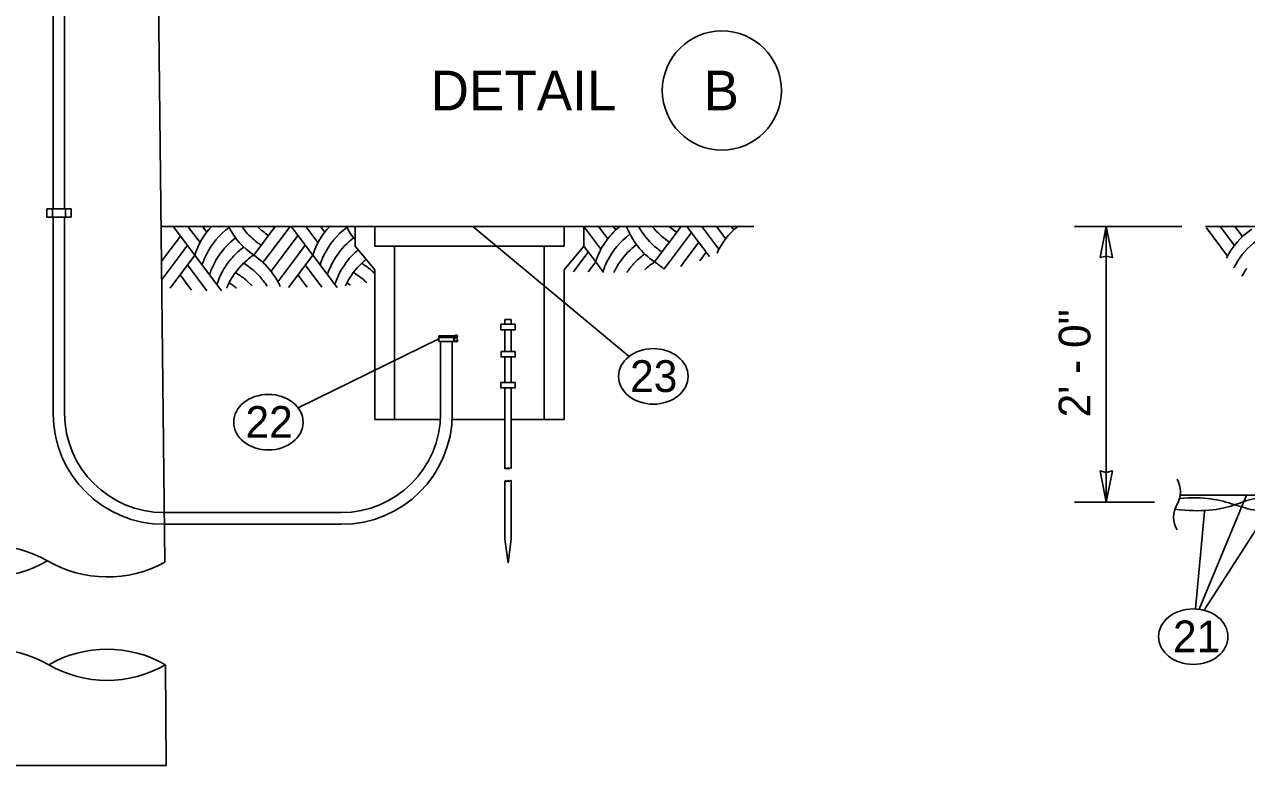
# Model space of a CAD drawing. Extents: x 99862 to 104211, y 98939 to 102076.
# Drawn here: x 100173 to 100788, y 100738 to 101111 of the extents above; entities that cross this region are included whole.
import ezdxf

# ---------------------------------------------------------------- set-up
doc = ezdxf.new("R2010")
doc.units = 0
for name, color, linetype in [('Level 1', 7, 'Continuous'), ('Level 11', 7, 'Continuous'), ('Level 13', 7, 'Continuous'), ('Level 15', 7, 'Continuous'), ('Level 20', 7, 'Continuous'), ('Level 7', 7, 'Continuous'), ('Level 8', 7, 'Continuous')]:
    doc.layers.add(name, color=color, linetype=linetype)

msp = doc.modelspace()

# ---------------------------------------------------------------- linework, layer by layer
at = {"layer": 'Level 1'}
for p, q in [((100243.61, 100840.23), (100238.01, 101340.94)), ((100244.35, 100737.75), (100243.96, 100788.54)), ((100244.35, 100737.75), (100124.97, 100737.75))]:
    msp.add_line(p, q, dxfattribs=at)
for centre, radius, start, end in [((100155.12, 100789.93), 58.82, 60, 120), ((100155.12, 100891.81), 58.82, 240, 300), ((100214.64, 100893.22), 60.4, 240.09406, 298.66389), ((100155.25, 100736.77), 59.78, 60, 120), ((100214.55, 100737.6), 58.82, 60, 120), ((100214.55, 100839.49), 58.82, 240, 300)]:
    msp.add_arc(centre, radius, start, end, dxfattribs=at)
at = {"layer": 'Level 11'}
msp.add_line((100810.77, 100874.11), (100755.06, 100874.11), dxfattribs=at)
for points in [[(100809.24, 100871.12), (100794.89, 100874.79), (100783.46, 100867.92), (100766.15, 100865.27), (100752.4, 100866.99)], [(100809.24, 100867.94), (100796.06, 100864.31), (100783.06, 100869.64), (100766.93, 100873.64), (100754.71, 100872.33)]]:
    msp.add_open_spline(points, degree=3, dxfattribs=at)
at = {"layer": 'Level 13'}
for p, q in [((100339.44, 101009.51), (100241.94, 101009.51)), ((100242.13, 100992.19), (100251.48, 101004.66)), ((100247.84, 101009.51), (100258.71, 100995.02)), ((100255.27, 101009.51), (100261.39, 101001.35)), ((100262.69, 101009.51), (100264.83, 101006.66)), ((100288.41, 100995.02), (100299.28, 101009.51)), ((100295.83, 100995.02), (100306.7, 101009.51)), ((100303.26, 100995.02), (100310.68, 101004.92)), ((100307.24, 101009.51), (100318.11, 100995.02)), ((100314.66, 101009.51), (100320.78, 101001.35)), ((100322.09, 101009.51), (100324.22, 101006.66)), ((100454.61, 101009.51), (100540.36, 101009.51)), ((100454.66, 101009.51), (100463.32, 100997.97)), ((100462.09, 101009.51), (100466.76, 101003.28)), ((100469.51, 101009.51), (100470.84, 101007.74)), ((100490.34, 100991.63), (100503.75, 101009.51)), ((100497.77, 100991.63), (100508.91, 101006.48)), ((100506.63, 101009.51), (100518.01, 100994.34)), ((100514.06, 101009.51), (100522.72, 100997.97)), ((100521.48, 101009.51), (100526.16, 101003.28)), ((100528.91, 101009.51), (100530.24, 101007.74)), ((100922.38, 101009.51), (100767.83, 101009.51)), ((100768.26, 101008.75), (100778.88, 100994.58)), ((100775.11, 101009.51), (100782.32, 100999.89)), ((100782.53, 101009.51), (100786.4, 101004.35)), ((100251.29, 100995.02), (100255, 100999.97)), ((100310.68, 100995.02), (100314.39, 100999.97)), ((100454.54, 100999.78), (100460.65, 100991.63)), ((100505.19, 100991.63), (100512.62, 101001.53)), ((100242.23, 100982.94), (100251.29, 100995.02)), ((100246.25, 100978.4), (100258.71, 100995.02)), ((100258.71, 100995.02), (100272.16, 100977.09)), ((100293.06, 100991.32), (100295.83, 100995.02)), ((100297.14, 100986.86), (100303.26, 100995.02)), ((100300.58, 100981.55), (100310.68, 100995.02)), ((100305.85, 100978.68), (100318.11, 100995.02)), ((100318.11, 100995.02), (100330.37, 100978.66)), ((100449.48, 100986.64), (100453.22, 100991.63)), ((100453.22, 100991.63), (100456.93, 100996.58)), ((100456.82, 100986.53), (100460.65, 100991.63)), ((100460.65, 100991.63), (100464.63, 100986.33)), ((100495, 100987.94), (100497.77, 100991.63)), ((100503.47, 100989.33), (100505.19, 100991.63)), ((100513.03, 100992.19), (100516.33, 100996.58)), ((100255, 100990.07), (100264.76, 100977.06)), ((100314.39, 100990.07), (100322.78, 100978.88)), ((100251.29, 100985.12), (100257.15, 100977.3)), ((100310.68, 100985.12), (100315.31, 100978.94))]:
    msp.add_line(p, q, dxfattribs=at)
for centre, start, end in [((100294.52, 100983.63), 136.46732, 162.3566), ((100298.23, 100978.68), 126.30625, 154.2266), ((100301.95, 100973.73), 127.1006, 145.49109), ((100309.37, 101026.21), 206.37862, 236.09639), ((100313.08, 101031.16), 215.17125, 228.95992), ((100316.79, 101036.11), 225.05162, 236.09639), ((100353.92, 100983.63), 136.46732, 162.3566), ((100357.63, 100978.68), 126.30625, 154.2266), ((100361.34, 100973.73), 127.1006, 145.49109), ((100368.77, 101026.21), 206.37862, 206.99593), ((100368.77, 101026.21), 206.99593, 218.71233), ((100496.46, 100980.24), 128.84684, 162.3566), ((100500.17, 100975.29), 126.30625, 154.2266), ((100511.31, 101022.82), 200.74709, 236.09639), ((100515.02, 101027.77), 209.07571, 228.95992), ((100518.73, 101032.72), 218.14737, 220.94161), ((100518.73, 101032.72), 220.94154, 236.09639), ((100522.44, 101037.67), 228.53909, 236.09639), ((100555.85, 100980.24), 128.84684, 155.08394), ((100812.02, 100976.86), 123.90361, 153.86997), ((100305.66, 100968.78), 126.331, 135.71278), ((100313.08, 101031.16), 228.95986, 236.09639), ((100365.05, 100968.78), 129.75344, 135.71278), ((100503.88, 100970.34), 127.1006, 145.49109), ((100515.02, 101027.77), 228.95986, 236.09639), ((100815.73, 100971.91), 126.30625, 150.60137), ((100298.23, 100978.68), 157.41388, 162.3566), ((100298.23, 100978.68), 154.22654, 157.41388), ((100301.95, 100973.73), 150.84712, 157.88414), ((100301.95, 100973.73), 145.49102, 150.84712), ((100305.66, 100968.78), 135.71269, 144.02067), ((100309.37, 100963.83), 123.90361, 136.7877), ((100267.45, 100963.83), 37.30083, 56.09634), ((100357.63, 100978.68), 154.22654, 162.3566), ((100361.34, 100973.73), 145.49102, 162.3566), ((100365.05, 100968.78), 135.71269, 161.92163), ((100368.77, 100963.83), 129.25852, 133.21419), ((100500.17, 100975.29), 154.22654, 161.70071), ((100503.88, 100970.34), 145.49102, 153.26545), ((100507.59, 100965.39), 135.71269, 144.09435), ((100507.59, 100965.39), 126.331, 135.71278), ((100511.31, 100960.44), 123.90361, 133.61086), ((100469.38, 100960.44), 46.9632, 56.09634), ((100301.95, 100973.73), 157.88414, 162.3566), ((100305.66, 100968.78), 150.82317, 162.3566), ((100305.66, 100968.78), 144.02067, 150.82317), ((100309.37, 100963.83), 143.40033, 148.16643), ((100309.37, 100963.83), 136.7877, 143.40033), ((100260.02, 100953.93), 59.26875, 59.30215), ((100260.02, 100953.93), 50.83623, 59.26875), ((100263.74, 100958.88), 52.41785, 58.54646), ((100263.74, 100958.88), 48.95968, 52.41785), ((100263.74, 100958.88), 43.21888, 48.95975), ((100267.45, 100963.83), 31.51956, 37.30083), ((100368.77, 100963.83), 133.21419, 153.69554), ((100319.42, 100953.93), 51.0642, 59.30215), ((100323.13, 100958.88), 58.01764, 58.54646), ((100323.13, 100958.88), 48.95968, 58.01764), ((100323.13, 100958.88), 45.65731, 48.95975), ((100503.88, 100970.34), 154.84124, 154.96351), ((100503.88, 100970.34), 153.82824, 154.84124), ((100503.88, 100970.34), 153.54486, 153.82824), ((100503.88, 100970.34), 153.26545, 153.54486), ((100507.59, 100965.39), 144.89013, 146.35794), ((100507.59, 100965.39), 144.48923, 144.89013), ((100507.59, 100965.39), 144.09435, 144.48923), ((100815.73, 100971.91), 153.1352, 153.5755), ((100815.73, 100971.91), 152.73447, 153.1352), ((100815.73, 100971.91), 151.65183, 152.73447), ((100815.73, 100971.91), 150.60137, 151.65183), ((100819.44, 100966.96), 150.65236, 152.41937), ((100819.44, 100966.96), 148.62082, 150.65236), ((100819.44, 100966.96), 146.25227, 148.62082), ((100819.44, 100966.96), 145.87013, 146.25227), ((100819.44, 100966.96), 145.49102, 145.87013), ((100309.37, 100963.83), 155.03105, 157.29034), ((100309.37, 100963.83), 152.34938, 155.03105), ((100256.31, 100948.98), 54.69221, 58.48737), ((100309.37, 100963.83), 148.16643, 152.34938), ((100256.31, 100948.98), 51.55439, 54.69221), ((100260.02, 100953.93), 45.59809, 50.83623), ((100260.02, 100953.93), 42.84548, 45.59809), ((100263.74, 100958.88), 38.33999, 43.21888), ((100263.74, 100958.88), 34.90419, 38.33999), ((100263.74, 100958.88), 33.01342, 34.90419), ((100267.45, 100963.83), 28.05833, 31.51956), ((100267.45, 100963.83), 25.58265, 28.05833), ((100267.45, 100963.83), 24.21668, 25.58265), ((100365.05, 100968.78), 161.92163, 162.3566), ((100368.77, 100963.83), 154.81157, 155.15216), ((100368.77, 100963.83), 154.15895, 154.81157), ((100368.77, 100963.83), 153.95763, 154.15895), ((100368.77, 100963.83), 153.69554, 153.95763), ((100315.71, 100948.98), 57.12601, 58.48737), ((100315.71, 100948.98), 56.72985, 57.12601), ((100315.71, 100948.98), 56.42149, 56.72985), ((100315.71, 100948.98), 55.43093, 56.42149), ((100319.42, 100953.93), 46.24597, 51.0642)]:
    msp.add_arc(centre, 37.58, start, end, dxfattribs=at)
at = {"layer": 'Level 15'}
for p, q in [((100477.55, 100944.01), (100398.82, 101009.51)), ((100755.83, 101009.51), (100701.83, 101009.51)), ((100717.83, 101009.51), (100717.83, 100870.52)), ((100310.78, 100918.07), (100381.68, 100952.88)), ((100742.06, 100870.52), (100701.83, 100870.52)), ((100764.55, 100816.53), (100788.46, 100874.11)), ((100762.79, 100816.7), (100767.25, 100865.81)), ((100767.13, 100816.02), (100799.54, 100866.56))]:
    msp.add_line(p, q, dxfattribs=at)
for points in [[(100717.83, 101009.51), (100714.75, 100993.78), (100717.83, 100994.51), (100720.91, 100993.78)], [(100717.83, 100870.52), (100714.75, 100886.24), (100717.83, 100885.52), (100720.91, 100886.24)]]:
    msp.add_lwpolyline(points, close=True, dxfattribs=at)
for centre, start, end in [((100742.36, 100875.69), 330, 30), ((100764.52, 100862.89), 150, 210)]:
    msp.add_arc(centre, 12.79, start, end, dxfattribs=at)
at = {"layer": 'Level 20'}
msp.add_circle((100524.21, 101078), 30, dxfattribs=at)
for centre in [(100489.68, 100933.91), (100295.81, 100910.81), (100761.61, 100802.73)]:
    msp.add_ellipse(centre, major_axis=(-17.5, 0), ratio=0.8, dxfattribs=at)
at = {"layer": 'Level 7'}
for p, q in [((100187.46, 101018.38), (100187.46, 101155.12)), ((100193.17, 101018.38), (100193.17, 101155.12)), ((100187.46, 100915.09), (100187.46, 101014.1)), ((100193.17, 100915.25), (100193.17, 101014.1)), ((100349.4, 101009.51), (100339.44, 101009.51)), ((100339.44, 101009.51), (100339.44, 100999.56)), ((100349.4, 100999.56), (100349.4, 101009.51)), ((100349.4, 101009.51), (100444.69, 101009.51)), ((100444.69, 101009.51), (100444.69, 100999.56)), ((100444.69, 101009.51), (100454.61, 101009.51)), ((100454.61, 101009.51), (100454.61, 100999.56)), ((100339.44, 100999.56), (100349.4, 100987.65)), ((100444.69, 100999.56), (100349.4, 100999.56)), ((100359.32, 100912.17), (100359.32, 100999.56)), ((100434.77, 100912.17), (100434.77, 100999.56)), ((100454.61, 100999.56), (100444.69, 100987.65)), ((100349.4, 100987.65), (100349.4, 100912.17)), ((100444.69, 100987.65), (100444.69, 100912.17)), ((100418.08, 100962.6), (100414.9, 100962.6)), ((100414.9, 100960.18), (100414.9, 100962.6)), ((100418.08, 100960.18), (100418.08, 100962.6)), ((100414.9, 100946.42), (100414.9, 100957.45)), ((100418.08, 100946.42), (100418.08, 100957.45)), ((100389.27, 100953.48), (100381.68, 100953.48)), ((100382.51, 100951.48), (100382.51, 100915.25)), ((100388.43, 100951.48), (100388.43, 100915.09)), ((100414.9, 100930.82), (100414.9, 100943.69)), ((100418.08, 100930.82), (100418.08, 100943.69)), ((100414.89, 100887.55), (100414.89, 100928.06)), ((100418.08, 100928.06), (100418.08, 100887.55)), ((100349.4, 100912.17), (100359.32, 100912.17)), ((100382.51, 100912.17), (100359.32, 100912.17)), ((100414.89, 100912.17), (100388.43, 100912.17)), ((100434.77, 100912.17), (100418.08, 100912.17)), ((100444.69, 100912.17), (100434.77, 100912.17)), ((100415.27, 100887.15), (100414.89, 100887.55)), ((100416.04, 100887.15), (100415.27, 100887.95)), ((100415.27, 100887.95), (100415.27, 100887.15)), ((100416.49, 100887.95), (100416.04, 100887.15)), ((100416.91, 100887.15), (100416.49, 100887.95)), ((100417.68, 100887.95), (100416.91, 100887.15)), ((100418.08, 100887.55), (100417.68, 100887.95)), ((100415.27, 100880.77), (100414.89, 100881.17)), ((100414.9, 100851.89), (100414.89, 100881.17)), ((100416.04, 100880.77), (100415.27, 100881.57)), ((100415.27, 100881.57), (100415.27, 100880.77)), ((100416.49, 100881.57), (100416.04, 100880.77)), ((100416.91, 100880.77), (100416.49, 100881.57)), ((100417.68, 100881.57), (100416.91, 100880.77)), ((100418.08, 100881.17), (100417.68, 100881.57)), ((100418.08, 100881.17), (100418.08, 100851.89)), ((100332.68, 100859.34), (100243.21, 100859.34)), ((100416.49, 100839.95), (100414.9, 100851.89)), ((100418.08, 100851.89), (100416.49, 100839.95))]:
    msp.add_line(p, q, dxfattribs=at)
for points in [[(100390.03, 100954.28), (100390.03, 100954.65), (100390.8, 100954.65), (100390.8, 100954.28)], [(100390.8, 100954.08), (100390.8, 100953.33), (100390.03, 100953.33), (100390.03, 100954.08)], [(100332.51, 100865.25), (100243.17, 100865.25)]]:
    msp.add_lwpolyline(points, dxfattribs=at)
for points in [[(100420.04, 100960.18), (100412.93, 100960.18), (100412.93, 100957.45), (100420.04, 100957.45)], [(100381.68, 100954.28), (100389.27, 100954.28), (100389.27, 100951.48), (100381.68, 100951.48)], [(100391.07, 100952.54), (100391.07, 100951.48), (100389.27, 100951.48), (100389.27, 100954.28), (100390.46, 100954.28), (100390.46, 100954.08), (100389.47, 100954.08), (100389.47, 100951.68), (100390.87, 100951.68), (100390.87, 100952.54)], [(100391.07, 100954.08), (100390.6, 100954.08), (100390.6, 100954.28), (100391.07, 100954.28)], [(100420.1, 100946.42), (100413.02, 100946.42), (100413.02, 100943.69), (100420.1, 100943.69)], [(100420.04, 100930.82), (100412.93, 100930.82), (100412.93, 100928.06), (100420.04, 100928.06)]]:
    msp.add_lwpolyline(points, close=True, dxfattribs=at)
for centre, radius, start, end in [((100243.21, 100915.09), 55.75, 180, 270), ((100243.17, 100915.25), 50, 180, 270), ((100332.51, 100915.25), 50, 270, 360), ((100332.68, 100915.09), 55.75, 270, 0)]:
    msp.add_arc(centre, radius, start, end, dxfattribs=at)
at = {"layer": 'Level 8'}
for p, q in [((100184.25, 101018.38), (100184.25, 101014.1)), ((100196.38, 101018.38), (100184.25, 101018.38)), ((100187.11, 101014.08), (100187.11, 101018.36)), ((100193.53, 101014.08), (100193.53, 101018.36)), ((100196.38, 101018.38), (100196.38, 101014.1)), ((100184.25, 101014.1), (100196.38, 101014.1))]:
    msp.add_line(p, q, dxfattribs=at)

# ---------------------------------------------------------------- texts
at = {"layer": 'Level 20'}
for s, height, p in [('DETAIL', 20, (100377.48, 101068)), ('B', 20, (100514.96, 101068)), ('23', 16, (100477.98, 100926.05)), ('22', 16, (100284.26, 100902.94)), ('21', 16, (100751.42, 100794.86))]:
    msp.add_text(s, height=height, dxfattribs=at).set_placement(p)
msp.add_text('2\' - 0"', height=16, rotation=90, dxfattribs=at).set_placement((100709.83, 100913.23))

doc.saveas('drawing.dxf')
